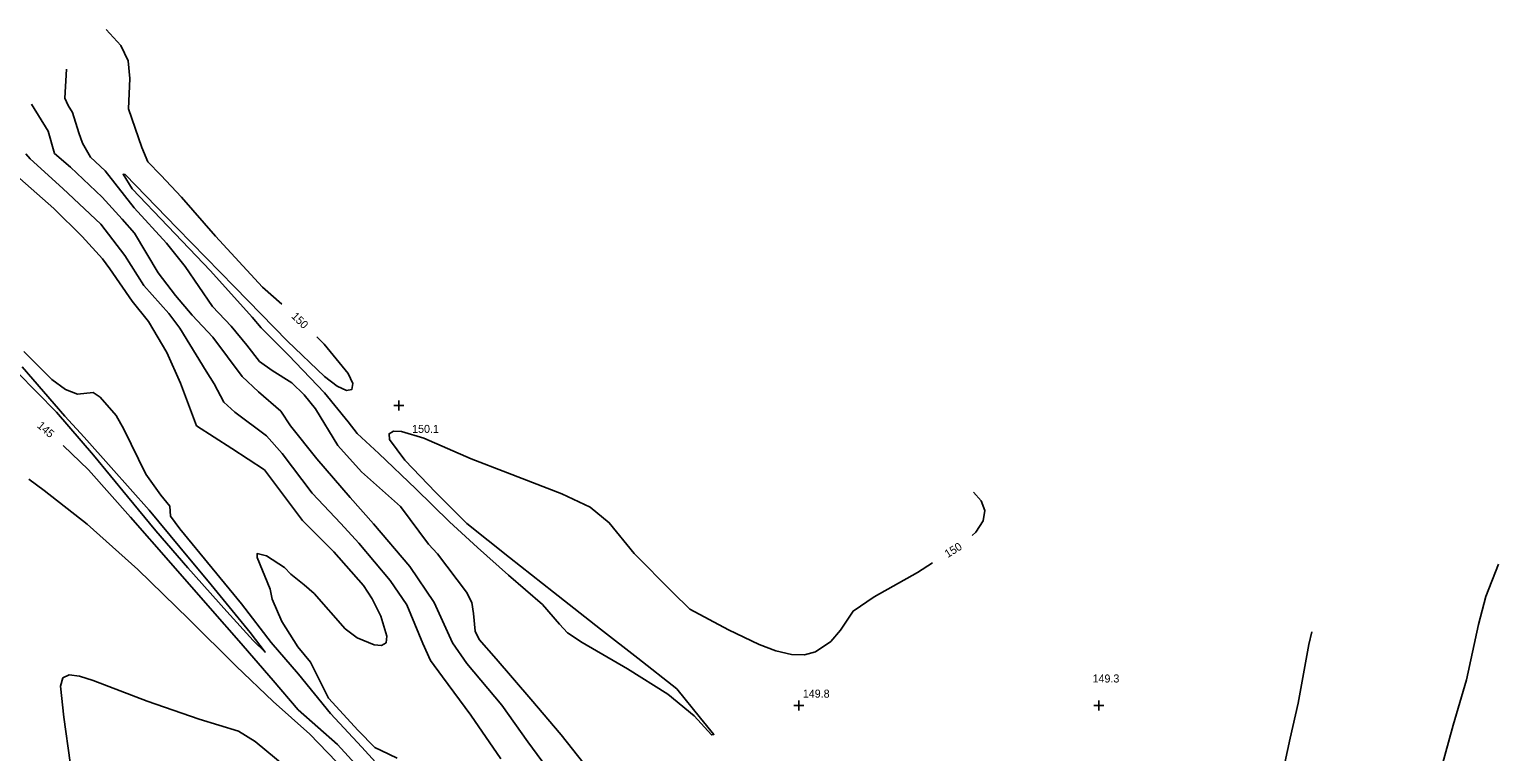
# Model space of a CAD drawing. Extents: x 1475150 to 2003689, y 770235 to 1112803.
# Drawn here: x 2001607.7 to 2001974.9, y 772388.4 to 772569.1 of the extents above; entities that cross this region are included whole.
import ezdxf

# ---------------------------------------------------------------- set-up
doc = ezdxf.new("R2010")
doc.units = 0
for name, color, linetype in [('RD_DTM_Major1', 7, 'Continuous'), ('RD_DTM_Major1_Lbl', 7, 'Continuous'), ('RD_DTM_Minor1', 7, 'Continuous'), ('RD_DTM_Spot_Elev', 7, 'Continuous')]:
    doc.layers.add(name, color=color, linetype=linetype)

msp = doc.modelspace()

# ---------------------------------------------------------------- linework, layer by layer
at = {"layer": 'RD_DTM_Major1'}
for points in [[(2001626.89, 772569.1), (2001630.55, 772565.08), (2001632.38, 772561.26), (2001632.75, 772556.79), (2001632.43, 772549.23), (2001635.74, 772539.55), (2001637.31, 772535.95), (2001640.52, 772532.62), (2001645.7, 772527.16), (2001654.19, 772517.41), (2001665.93, 772504.59), (2001670.78, 772500.39)], [(2001679.52, 772492.16), (2001681.32, 772490.38), (2001687.33, 772483.02), (2001688.49, 772480.49), (2001688.31, 772479.05), (2001686.96, 772478.81), (2001684.61, 772479.86), (2001681.4, 772482.29), (2001672.2, 772491.12), (2001658.92, 772504.72), (2001644.61, 772519.37), (2001631.6, 772532.78), (2001631.1, 772532.84), (2001633.39, 772529.21), (2001642.27, 772519.86), (2001652.96, 772508.66), (2001663.36, 772497.08), (2001665.57, 772494.41), (2001672.47, 772487.63), (2001681.4, 772478.17), (2001687.38, 772470.95), (2001689.63, 772468.03), (2001695.04, 772463.04), (2001704.25, 772454.17), (2001712.71, 772445.93), (2001719.7, 772439.53), (2001727.45, 772432.55), (2001735.9, 772425.27), (2001740.16, 772420.32), (2001742.2, 772418.13), (2001745.81, 772415.7), (2001757.2, 772409.13), (2001767.23, 772402.84), (2001773.86, 772397.44), (2001778.16, 772392.61), (2001778.79, 772392.75), (2001775.46, 772396.82), (2001769.52, 772404.13), (2001759.74, 772411.79), (2001750.4, 772419.09), (2001738.68, 772428.29), (2001727.69, 772436.98), (2001716.99, 772445.49), (2001709.25, 772453.26), (2001701.51, 772461.31), (2001697.68, 772466.51), (2001697.58, 772467.96), (2001698.69, 772468.6), (2001700.69, 772468.53), (2001706.29, 772466.83), (2001718.09, 772461.64), (2001727.15, 772458.2), (2001740.75, 772452.94), (2001747.85, 772449.55), (2001752.6, 772445.69), (2001758.81, 772437.96), (2001768.42, 772428.3), (2001772.79, 772424.05), (2001782.44, 772418.95), (2001790.07, 772415.27), (2001794.26, 772413.69), (2001798.16, 772412.74), (2001801.45, 772412.69), (2001804.14, 772413.39), (2001808, 772416), (2001810.38, 772418.84), (2001813.56, 772423.6), (2001818.81, 772427.17), (2001829.65, 772433.25), (2001833.45, 772435.64)], [(2001606.3, 772488.54), (2001613.25, 772481.55), (2001616.66, 772478.98), (2001619.7, 772477.88), (2001623.59, 772478.31), (2001625.35, 772477.08), (2001629.39, 772472.5), (2001631.3, 772469.12), (2001636.74, 772457.86), (2001640.51, 772452.57), (2001642.8, 772449.86), (2001642.93, 772447.36), (2001645.29, 772444.18), (2001653.4, 772434.36), (2001660.65, 772425.4), (2001668.09, 772415.75), (2001674.93, 772407.81), (2001682.96, 772397.98), (2001690.8, 772389.56), (2001698.44, 772381.18)], [(2001691.81, 772382.51), (2001684.69, 772390.21), (2001674.86, 772398.94), (2001668.57, 772406.22), (2001660.04, 772416.12), (2001653.43, 772423.64), (2001642.99, 772435.56), (2001632.97, 772447.06), (2001622.46, 772458.96), (2001616.14, 772465.02)], [(2001843.3, 772442.52), (2001844.22, 772443.34), (2001846.11, 772446.16), (2001846.52, 772448.74), (2001845.59, 772451.14), (2001843.64, 772453.38)], [(2001928.21, 772418.45), (2001927.5, 772415.27), (2001924.85, 772400.56), (2001922.85, 772391.8), (2001919.52, 772376.36), (2001918.9, 772372.55)]]:
    msp.add_lwpolyline(points, dxfattribs=at)
at = {"layer": 'RD_DTM_Minor1'}
for points in [[(2001616.95, 772559.15), (2001616.56, 772551.86), (2001617.33, 772550.06), (2001618.48, 772548.34), (2001620.03, 772543.21), (2001620.93, 772540.63), (2001622.94, 772537.12), (2001626.59, 772533.69), (2001633.85, 772524.44), (2001641.92, 772515.65), (2001646.6, 772509.76), (2001653.46, 772499.76), (2001658.13, 772494.84), (2001661.99, 772490.09), (2001665.21, 772486.06), (2001668.35, 772483.74), (2001673.25, 772480.68), (2001676.37, 772477.72), (2001679.18, 772474.22), (2001684.77, 772465.01), (2001690.67, 772458.46), (2001700.44, 772449.77), (2001707.4, 772440.31), (2001709.66, 772437.89), (2001716.91, 772428.29), (2001718.23, 772425.75), (2001718.64, 772423), (2001719.06, 772418.54), (2001720.13, 772416.46), (2001724.32, 772411.66), (2001733, 772401.54), (2001740.63, 772392.63), (2001749.08, 772381.91)], [(2001608.17, 772550.36), (2001612.34, 772543.65), (2001613.91, 772538.09), (2001617.96, 772534.62), (2001625.83, 772527.13), (2001630.87, 772521.63), (2001633.97, 772518.15), (2001639.84, 772508.2), (2001644.19, 772502.54), (2001648.36, 772497.64), (2001653.55, 772492.1), (2001660.84, 772482.28), (2001664.92, 772478.41), (2001670.5, 772473.58), (2001672.93, 772469.95), (2001679.53, 772461.72), (2001687.88, 772452.01), (2001693.67, 772445.46), (2001702.73, 772434.78), (2001708.83, 772425.74), (2001713.45, 772415.69), (2001717.03, 772410.45), (2001725.79, 772400.08), (2001732.25, 772390.87), (2001739.29, 772381.39)], [(2001606.78, 772537.99), (2001607.87, 772536.75), (2001616.05, 772529.3), (2001625.54, 772520.36), (2001631.53, 772512.52), (2001636.27, 772505.07), (2001642.54, 772498.02), (2001645.24, 772494.39), (2001651.86, 772483.59), (2001653.89, 772480.41), (2001656.28, 772475.83), (2001659, 772473.35), (2001666.97, 772467.41), (2001670.82, 772462.99), (2001678.32, 772453.1), (2001685.5, 772445.48), (2001689.98, 772440.56), (2001697.82, 772431.23), (2001702, 772425.2), (2001706.03, 772415.53), (2001707.94, 772411.28), (2001710.95, 772407.17), (2001718, 772397.56), (2001725.48, 772386.61)], [(2001605.25, 772531.76), (2001613.75, 772524.32), (2001620.89, 772517.25), (2001625.93, 772511.74), (2001627.77, 772509.21), (2001633.34, 772501.14), (2001637.41, 772496.05), (2001642.05, 772488.25), (2001645.43, 772480.58), (2001649.44, 772469.96), (2001658.31, 772464.23), (2001666.46, 772458.89), (2001669.66, 772454.6), (2001675.94, 772446.29), (2001683.73, 772438.43), (2001691.16, 772429.99), (2001693.39, 772426.67), (2001695.5, 772422.34), (2001697.05, 772417.35), (2001696.84, 772415.67), (2001695.67, 772414.98), (2001693.82, 772415.14), (2001689.61, 772416.89), (2001686.61, 772419.14), (2001678.82, 772427.97), (2001676.34, 772430.2), (2001672.99, 772432.86), (2001671.45, 772434.48), (2001666.93, 772437.44), (2001664.58, 772437.98), (2001664.63, 772437.01), (2001667.85, 772429.06), (2001668.33, 772426.55), (2001670.75, 772421.01), (2001674.74, 772414.64), (2001677.96, 772410.82), (2001682.47, 772401.81), (2001689.89, 772393.69), (2001694.03, 772389.45), (2001695.59, 772388.74), (2001699.63, 772386.81)], [(2001605.83, 772484.73), (2001616.57, 772472.32), (2001621.34, 772467.08), (2001628.15, 772459.49), (2001637.58, 772448.84), (2001645.24, 772439.62), (2001653.11, 772430.13), (2001662.86, 772418.25), (2001666.63, 772413.34), (2001663.58, 772416.2), (2001657.04, 772423.53), (2001647.31, 772434.44), (2001639.28, 772443.69), (2001632.19, 772452.24), (2001623.67, 772462.6), (2001614.41, 772473.37), (2001604.65, 772483.36)], [(2001686.68, 772383.59), (2001677.77, 772392.79), (2001668.57, 772400.95), (2001659.38, 772409.79), (2001647.53, 772421.56), (2001634.75, 772434.02), (2001622.12, 772445.37), (2001611.37, 772453.78), (2001607.54, 772456.56)], [(2001974.92, 772435.37), (2001971.74, 772427.28), (2001969.85, 772420.22), (2001966.9, 772406.38), (2001963.59, 772395.07), (2001960.59, 772384.13)], [(2001671.83, 772384.56), (2001664.12, 772391.02), (2001659.96, 772393.53), (2001650.11, 772396.55), (2001637.08, 772401.03), (2001623.58, 772406.2), (2001620.21, 772407.32), (2001617.65, 772407.65), (2001616.05, 772406.89), (2001615.45, 772404.79), (2001616.27, 772397.05), (2001617.88, 772385.73)]]:
    msp.add_lwpolyline(points, dxfattribs=at)
at = {"layer": 'RD_DTM_Spot_Elev'}
for p, q in [((2001700, 772473.75), (2001700, 772476.25)), ((2001698.75, 772475), (2001701.25, 772475)), ((2001798.75, 772400), (2001801.25, 772400)), ((2001800, 772398.75), (2001800, 772401.25)), ((2001873.75, 772400), (2001876.25, 772400)), ((2001875, 772398.75), (2001875, 772401.25))]:
    msp.add_line(p, q, dxfattribs=at)

# ---------------------------------------------------------------- texts
at = {"layer": 'RD_DTM_Major1_Lbl'}
for s, rotation, p in [('150', 315.4132, (2001673.01, 772497.17)), ('145', 319.0928, (2001609.44, 772469.71)), ('150', 32.2028, (2001837.23, 772436.84))]:
    msp.add_text(s, height=2, rotation=rotation, dxfattribs=at).set_placement(p)
at = {"layer": 'RD_DTM_Spot_Elev'}
for s, p in [('150.1', (2001703.34, 772468.18)), ('149.3', (2001873.42, 772405.74)), ('149.8', (2001801, 772401.95))]:
    msp.add_text(s, height=2, dxfattribs=at).set_placement(p)

doc.saveas('drawing.dxf')
